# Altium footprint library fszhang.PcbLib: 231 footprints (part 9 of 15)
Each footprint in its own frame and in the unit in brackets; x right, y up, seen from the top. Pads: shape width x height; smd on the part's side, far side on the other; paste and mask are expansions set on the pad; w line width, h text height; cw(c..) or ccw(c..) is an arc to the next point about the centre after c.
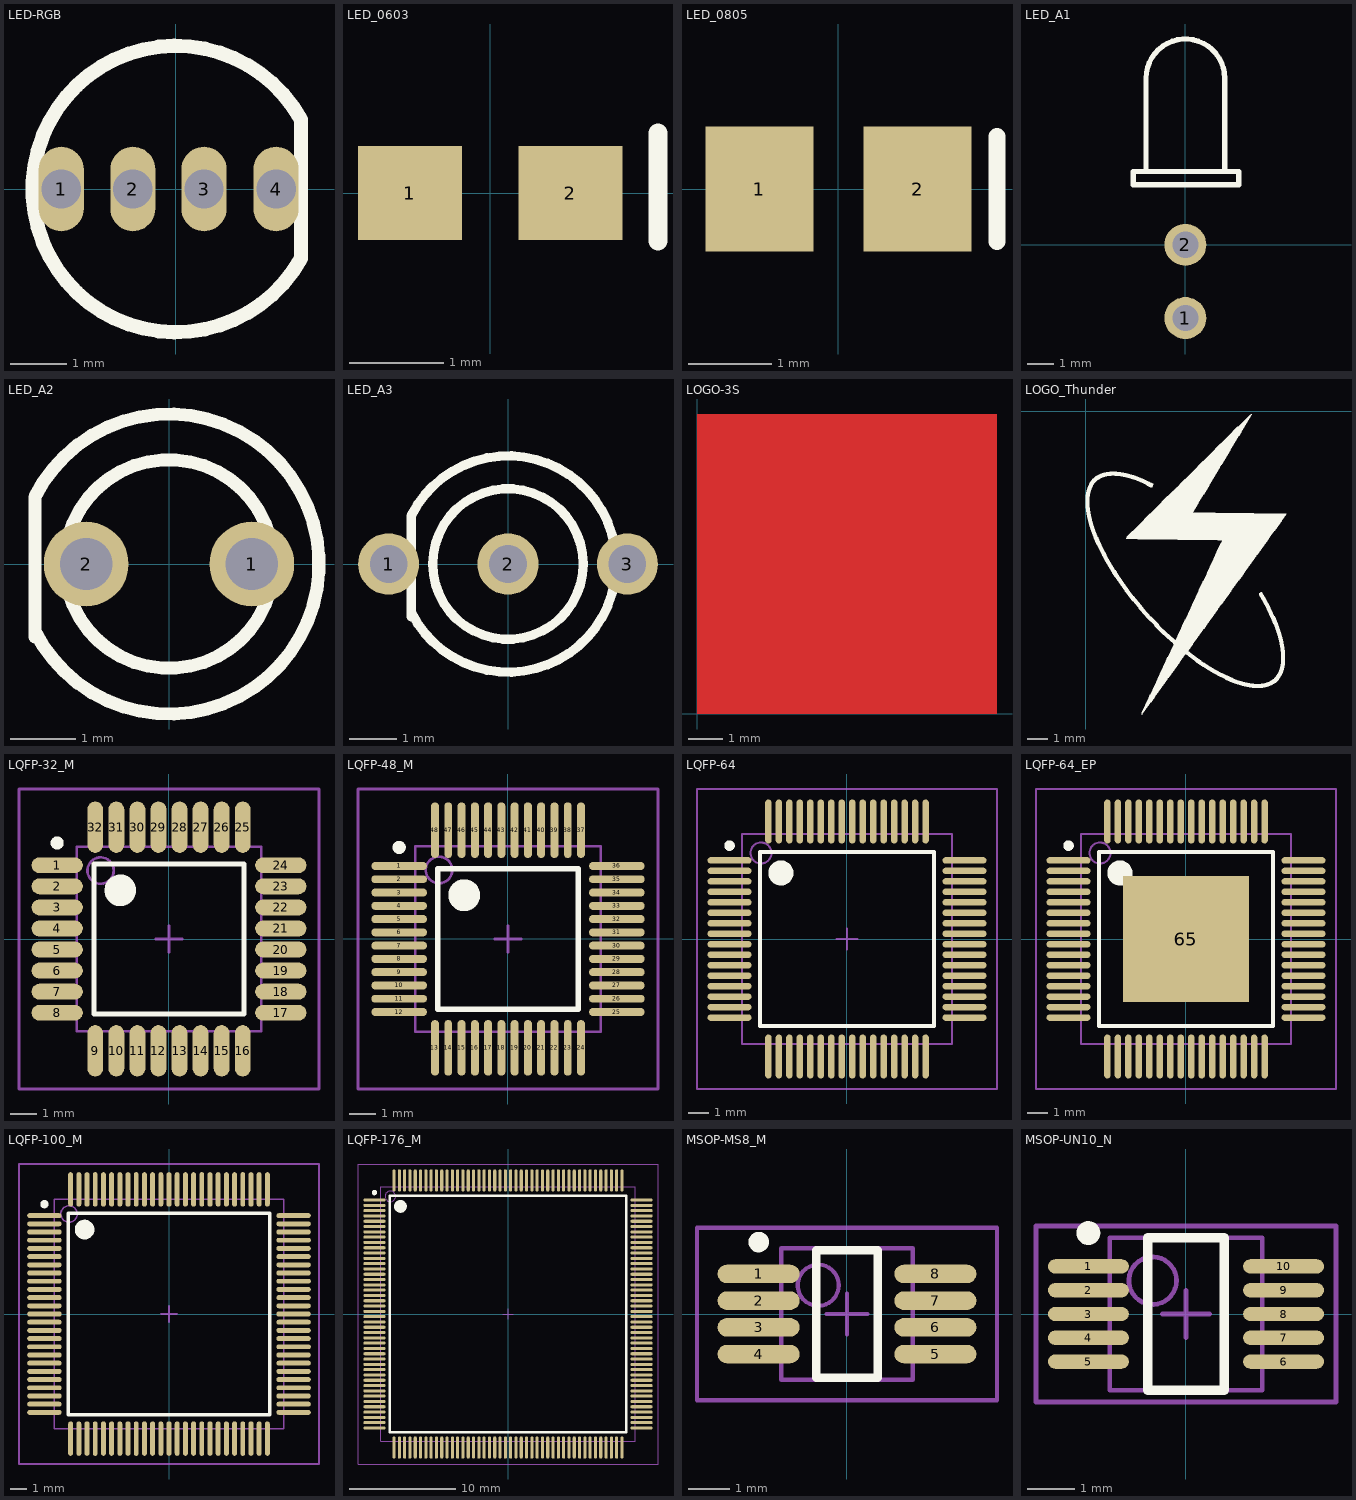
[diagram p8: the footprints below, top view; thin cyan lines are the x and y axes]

## LED-RGB [mm] "三基色二极管"
height 6
pads (4):
  oval 0.8x1.5 hole 0.7: 1(-2.032,0) 2(-0.762,0) 3(0.5,0) 4(1.778,0)
Top Overlay:
  lines w0.254: 2.22,-1.234 cw(c0,0) 2.22,1.234 2.22,-1.234

## LED_0603 [mm] "贴片无丝印"
height 0.6
pads (2):
  rect 1.1x1 smd: 1(-0.85,0) 2(0.85,0)
Top Overlay:
  lines w0.2: 1.778,-0.508 1.778,0.635

## LED_0805 [mm] "贴片二极管"
height 1.1
pads (2):
  rect 1.3x1.5 smd: 1(-0.95,0) 2(0.95,0)
Top Overlay:
  lines w0.2: 1.905,-0.635 1.905,0.635

## LED_A1 [mm] "直径3MM二极管"
height 3.5
pads (2):
  round 1.6 hole 1: 1(0,-2.794) 2(0,0)
Top Overlay:
  lines w0.2: -1.5,2.852 -1.5,6.35 cw(c0,6.35) 1.5,6.35 1.5,2.852 ; -1.984,2.286 2.032,2.286 2.032,2.794 -1.984,2.794 -1.984,2.286

## LED_A2 [mm] "直径3MM二极管"
height 5.5
pads (2):
  round 1.3 hole 0.8: 1(1.27,0) 2(-1.27,0)
Top Overlay:
  circle w0.2: c0,0 r1.6
  lines w0.2: -2.057,-1.118 -2.057,1.029 cw(c0,0) -2.057,-1.029

## LED_A3 [mm] "直径3MM二极管"
height 5.5
pads (3):
  round 1.3 hole 0.8: 1(-2.54,0) 2(0,0) 3(2.54,0)
Top Overlay:
  circle w0.2: c0,0 r1.6
  lines w0.2: -2.057,-1.118 -2.057,1.029 cw(c0,0) -2.057,-1.029

## LOGO-3S [mm]
Top Layer:
  rectangle: 0,0 8.8,8.8
Top Paste:
  circle w1.8: c4.399,4.401 r1.206
  region: 0.203,2.813 2.515,2.813 2.62,2.707 2.709,2.618 2.856,2.491 3.065,2.336 3.371,2.172 3.614,2.078 3.851,2.015 4.117,1.966 4.359,1.95 4.607,1.954 4.874,1.996 5.092,2.052 5.389,2.162 5.606,2.287 5.846,2.43 6.228,2.786 8.473,2.786 8.473,2.787 8.397,2.529 8.283,2.239 8.089,1.886 7.898,1.591 7.641,1.298 7.313,0.995 6.914,0.706 6.524,0.507 6.101,0.348 5.721,0.252 5.216,0.196 0.203,0.196
  region: 0.257,5.8 2.394,5.8 2.304,5.672 2.215,5.504 2.154,5.378 2.095,5.22 2.078,5.162 0.202,4.84 0.202,5.101 0.216,5.429 0.239,5.703
  region: 8.596,5.988 6.284,5.988 6.178,6.094 6.09,6.183 5.942,6.31 5.733,6.465 5.428,6.629 5.185,6.723 4.948,6.786 4.682,6.835 4.44,6.851 4.192,6.847 3.924,6.805 3.706,6.749 3.41,6.639 3.193,6.514 2.953,6.371 2.571,6.015 0.326,6.015 0.326,6.014 0.402,6.272 0.516,6.562 0.71,6.915 0.901,7.21 1.158,7.503 1.485,7.806 1.885,8.095 2.274,8.294 2.698,8.453 3.078,8.549 3.583,8.605 8.596,8.605
  region: 8.525,2.993 6.389,2.993 6.478,3.12 6.568,3.288 6.629,3.414 6.687,3.573 6.705,3.63 8.581,3.953 8.581,3.692 8.566,3.364 8.543,3.09
  region: 8.587,4.147 6.823,4.147 6.831,4.195 6.838,4.282 6.842,4.385 6.84,4.497 6.831,4.6 6.815,4.654 8.587,4.654
  region: 0.203,4.654 1.967,4.654 1.96,4.606 1.952,4.519 1.948,4.416 1.95,4.304 1.96,4.201 1.976,4.147 0.203,4.147
  region: 6.398,5.8 8.576,5.8 8.576,5.137 6.795,4.828 6.77,4.979 6.734,5.098 6.697,5.204 6.619,5.406 6.534,5.58
  region: 2.383,2.992 0.205,2.992 0.205,3.655 1.987,3.964 2.012,3.813 2.047,3.694 2.084,3.589 2.162,3.386 2.247,3.212
Top Solder:
  circle w1.8: c4.398,4.403 r1.206
  region: 0.202,2.815 2.514,2.815 2.62,2.709 2.709,2.62 2.856,2.493 3.065,2.338 3.37,2.174 3.613,2.08 3.85,2.017 4.116,1.968 4.358,1.952 4.606,1.956 4.874,1.998 5.092,2.054 5.388,2.164 5.605,2.289 5.845,2.432 6.228,2.788 8.472,2.788 8.472,2.789 8.396,2.531 8.282,2.241 8.088,1.888 7.897,1.593 7.64,1.3 7.313,0.997 6.913,0.708 6.524,0.509 6.1,0.35 5.72,0.254 5.215,0.198 0.202,0.198
  region: 0.257,5.802 2.393,5.802 2.304,5.674 2.214,5.506 2.153,5.38 2.095,5.222 2.077,5.164 0.201,4.842 0.201,5.103 0.216,5.431 0.239,5.705
  region: 8.595,5.99 6.283,5.99 6.178,6.096 6.089,6.185 5.942,6.312 5.733,6.467 5.427,6.631 5.184,6.725 4.947,6.788 4.681,6.837 4.439,6.853 4.191,6.849 3.924,6.807 3.706,6.751 3.409,6.641 3.192,6.516 2.952,6.373 2.57,6.017 0.325,6.017 0.325,6.016 0.401,6.274 0.515,6.564 0.709,6.917 0.9,7.212 1.157,7.505 1.485,7.808 1.884,8.097 2.274,8.296 2.697,8.455 3.077,8.551 3.582,8.607 8.595,8.607
  region: 8.524,2.995 6.388,2.995 6.477,3.122 6.567,3.29 6.628,3.416 6.687,3.575 6.704,3.632 8.58,3.955 8.58,3.694 8.565,3.366 8.542,3.092
  region: 8.587,4.149 6.823,4.149 6.83,4.197 6.838,4.284 6.841,4.387 6.839,4.499 6.83,4.602 6.814,4.656 8.587,4.656
  region: 0.203,4.656 1.967,4.656 1.959,4.608 1.952,4.521 1.948,4.418 1.95,4.306 1.959,4.203 1.975,4.149 0.203,4.149
  region: 6.397,5.802 8.575,5.802 8.575,5.139 6.794,4.83 6.769,4.981 6.734,5.1 6.697,5.206 6.619,5.408 6.533,5.582
  region: 2.383,2.994 0.205,2.994 0.205,3.657 1.986,3.966 2.011,3.815 2.046,3.696 2.083,3.591 2.161,3.388 2.247,3.214

## LOGO_Thunder [mm]
Top Overlay:
  drawing of 2284 lines, arcs and shapes, not listed

## LQFP-32_M [mm] "Thin QFP, 32-Leads, Body 7x7mm, Pitch 0.8mm, IPC Low Density"
height 1.6
pads (32):
  oval 1.95x0.6 smd: 1(-4.25,2.8) 2(-4.25,2) 3(-4.25,1.2) 4(-4.25,0.4) 5(-4.25,-0.4) 6(-4.25,-1.2) 7(-4.25,-2) 8(-4.25,-2.8) 17(4.25,-2.8) 18(4.25,-2) 19(4.25,-1.2) 20(4.25,-0.4) 21(4.25,0.4) 22(4.25,1.2) 23(4.25,2) 24(4.25,2.8)
  oval 0.6x1.95 smd: 9(-2.8,-4.25) 10(-2,-4.25) 11(-1.2,-4.25) 12(-0.4,-4.25) 13(0.4,-4.25) 14(1.2,-4.25) 15(2,-4.25) 16(2.8,-4.25) 25(2.8,4.25) 26(2,4.25) 27(1.2,4.25) 28(0.4,4.25) 29(-0.4,4.25) 30(-1.2,4.25) 31(-2,4.25) 32(-2.8,4.25)
Top Overlay:
  circle w0.25: c-4.25,3.65 r0.125
  circle w0.6: c-1.85,1.85 r0.3
  lines w0.2: -2.85,-2.85 -2.85,2.85 2.85,2.85 2.85,-2.85 -2.85,-2.85
Mechanical 13:
  circle w0.1: c-2.6,2.6 r0.5
  lines w0.1: -3.5,-3.5 -3.5,3.5 3.5,3.5 3.5,-3.5 -3.5,-3.5
Mechanical 15:
  lines w0.1: -0.5,0 0.5,0 ; 0,-0.5 0,0.5 ; -5.7,-5.7 -5.7,5.7 5.7,5.7 5.7,-5.7 -5.7,-5.7
3D body: height 1.6, standoff 0, extent -3.5,-3.5 3.5,3.5

## LQFP-48_M [mm] "Thin QFP, 48-Leads, Body 7x7mm, Pitch 0.5mm, IPC Low Density"
height 1.6
pads (48):
  oval 2.1x0.3 smd: 1(-4.1,2.75) 2(-4.1,2.25) 3(-4.1,1.75) 4(-4.1,1.25) 5(-4.1,0.75) 6(-4.1,0.25) 7(-4.1,-0.25) 8(-4.1,-0.75) 9(-4.1,-1.25) 10(-4.1,-1.75) 11(-4.1,-2.25) 12(-4.1,-2.75) 25(4.1,-2.75) 26(4.1,-2.25) 27(4.1,-1.75) 28(4.1,-1.25) 29(4.1,-0.75) 30(4.1,-0.25) 31(4.1,0.25) 32(4.1,0.75) 33(4.1,1.25) 34(4.1,1.75) 35(4.1,2.25) 36(4.1,2.75)
  oval 0.3x2.1 smd: 13(-2.75,-4.1) 14(-2.25,-4.1) 15(-1.75,-4.1) 16(-1.25,-4.1) 17(-0.75,-4.1) 18(-0.25,-4.1) 19(0.25,-4.1) 20(0.75,-4.1) 21(1.25,-4.1) 22(1.75,-4.1) 23(2.25,-4.1) 24(2.75,-4.1) 37(2.75,4.1) 38(2.25,4.1) 39(1.75,4.1) 40(1.25,4.1) 41(0.75,4.1) 42(0.25,4.1) 43(-0.25,4.1) 44(-0.75,4.1) 45(-1.25,4.1) 46(-1.75,4.1) 47(-2.25,4.1) 48(-2.75,4.1)
Top Overlay:
  circle w0.6: c-1.65,1.65 r0.3
  circle w0.25: c-4.1,3.45 r0.125
  lines w0.2: -2.65,-2.65 2.65,-2.65 2.65,2.65 -2.65,2.65 -2.65,-2.65
Mechanical 13:
  circle w0.1: c-2.6,2.6 r0.5
  lines w0.1: -3.5,-3.5 3.5,-3.5 3.5,3.5 -3.5,3.5 -3.5,-3.5
Mechanical 15:
  lines w0.1: -0.5,0 0.5,0 ; 0,-0.5 0,0.5 ; -5.65,-5.65 5.65,-5.65 5.65,5.65 -5.65,5.65 -5.65,-5.65
3D body: height 1.6, standoff 0, extent -3.5,-3.5 3.5,3.5

## LQFP-64 [mm] "LQFP64"
height 1.5
pads (64):
  oval 2.1x0.3 smd: 1(-5.6,3.75) 2(-5.6,3.25) 3(-5.6,2.75) 4(-5.6,2.25) 5(-5.6,1.75) 6(-5.6,1.25) 7(-5.6,0.75) 8(-5.6,0.25) 9(-5.6,-0.25) 10(-5.6,-0.75) 11(-5.6,-1.25) 12(-5.6,-1.75) 13(-5.6,-2.25) 14(-5.6,-2.75) 15(-5.6,-3.25) 16(-5.6,-3.75) 33(5.6,-3.75) 34(5.6,-3.25) 35(5.6,-2.75) 36(5.6,-2.25) 37(5.6,-1.75) 38(5.6,-1.25) 39(5.6,-0.75) 40(5.6,-0.25) 41(5.6,0.25) 42(5.6,0.75) 43(5.6,1.25) 44(5.6,1.75) 45(5.6,2.25) 46(5.6,2.75) 47(5.6,3.25) 48(5.6,3.75)
  oval 0.3x2.1 smd: 17(-3.75,-5.6) 18(-3.25,-5.6) 19(-2.75,-5.6) 20(-2.25,-5.6) 21(-1.75,-5.6) 22(-1.25,-5.6) 23(-0.75,-5.6) 24(-0.25,-5.6) 25(0.25,-5.6) 26(0.75,-5.6) 27(1.25,-5.6) 28(1.75,-5.6) 29(2.25,-5.6) 30(2.75,-5.6) 31(3.25,-5.6) 32(3.75,-5.6) 49(3.75,5.6) 50(3.25,5.6) 51(2.75,5.6) 52(2.25,5.6) 53(1.75,5.6) 54(1.25,5.6) 55(0.75,5.6) 56(0.25,5.6) 57(-0.25,5.6) 58(-0.75,5.6) 59(-1.25,5.6) 60(-1.75,5.6) 61(-2.25,5.6) 62(-2.75,5.6) 63(-3.25,5.6) 64(-3.75,5.6)
Top Overlay:
  circle w0.6: c-3.15,3.15 r0.3
  circle w0.25: c-5.6,4.45 r0.125
  lines w0.2: -4.15,-4.15 4.15,-4.15 4.15,4.15 -4.15,4.15 -4.15,-4.15
Mechanical 13:
  circle w0.1: c-4.1,4.1 r0.5
  lines w0.1: -5,-5 5,-5 5,5 -5,5 -5,-5
Mechanical 15:
  lines w0.1: -0.5,0 0.5,0 ; 0,-0.5 0,0.5 ; -7.15,-7.15 7.15,-7.15 7.15,7.15 -7.15,7.15 -7.15,-7.15
3D body: height 1.6, standoff 0, extent -5,-5 5,5

## LQFP-64_EP [mm] "LQFP64"
height 1.5
pads (65):
  oval 2.1x0.3 smd: 1(-5.6,3.75) 2(-5.6,3.25) 3(-5.6,2.75) 4(-5.6,2.25) 5(-5.6,1.75) 6(-5.6,1.25) 7(-5.6,0.75) 8(-5.6,0.25) 9(-5.6,-0.25) 10(-5.6,-0.75) 11(-5.6,-1.25) 12(-5.6,-1.75) 13(-5.6,-2.25) 14(-5.6,-2.75) 15(-5.6,-3.25) 16(-5.6,-3.75) 33(5.6,-3.75) 34(5.6,-3.25) 35(5.6,-2.75) 36(5.6,-2.25) 37(5.6,-1.75) 38(5.6,-1.25) 39(5.6,-0.75) 40(5.6,-0.25) 41(5.6,0.25) 42(5.6,0.75) 43(5.6,1.25) 44(5.6,1.75) 45(5.6,2.25) 46(5.6,2.75) 47(5.6,3.25) 48(5.6,3.75)
  oval 0.3x2.1 smd: 17(-3.75,-5.6) 18(-3.25,-5.6) 19(-2.75,-5.6) 20(-2.25,-5.6) 21(-1.75,-5.6) 22(-1.25,-5.6) 23(-0.75,-5.6) 24(-0.25,-5.6) 25(0.25,-5.6) 26(0.75,-5.6) 27(1.25,-5.6) 28(1.75,-5.6) 29(2.25,-5.6) 30(2.75,-5.6) 31(3.25,-5.6) 32(3.75,-5.6) 49(3.75,5.6) 50(3.25,5.6) 51(2.75,5.6) 52(2.25,5.6) 53(1.75,5.6) 54(1.25,5.6) 55(0.75,5.6) 56(0.25,5.6) 57(-0.25,5.6) 58(-0.75,5.6) 59(-1.25,5.6) 60(-1.75,5.6) 61(-2.25,5.6) 62(-2.75,5.6) 63(-3.25,5.6) 64(-3.75,5.6)
  rect 6x6 smd: 65(0,0)
Top Overlay:
  circle w0.25: c-5.6,4.45 r0.125
  circle w0.6: c-3.15,3.15 r0.3
  lines w0.2: -4.15,-4.15 -4.15,4.15 4.15,4.15 4.15,-4.15 -4.15,-4.15
Mechanical 13:
  circle w0.1: c-4.1,4.1 r0.5
  lines w0.1: -5,-5 -5,5 5,5 5,-5 -5,-5
Mechanical 15:
  lines w0.1: -0.5,0 0.5,0 ; 0,-0.5 0,0.5 ; -7.15,-7.15 -7.15,7.15 7.15,7.15 7.15,-7.15 -7.15,-7.15
3D body: height 1.6, standoff 0, extent -5,-5 5,5

## LQFP-100_M [mm] "Thin QFP, 100"
height 1.6
pads (100):
  oval 2.1x0.3 smd: 1(-7.6,6) 2(-7.6,5.5) 3(-7.6,5) 4(-7.6,4.5) 5(-7.6,4) 6(-7.6,3.5) 7(-7.6,3) 8(-7.6,2.5) 9(-7.6,2) 10(-7.6,1.5) 11(-7.6,1) 12(-7.6,0.5) 13(-7.6,0) 14(-7.6,-0.5) 15(-7.6,-1) 16(-7.6,-1.5) 17(-7.6,-2) 18(-7.6,-2.5) 19(-7.6,-3) 20(-7.6,-3.5) 21(-7.6,-4) 22(-7.6,-4.5) 23(-7.6,-5) 24(-7.6,-5.5) 25(-7.6,-6) 51(7.6,-6) 52(7.6,-5.5) 53(7.6,-5) 54(7.6,-4.5) 55(7.6,-4) 56(7.6,-3.5) 57(7.6,-3) 58(7.6,-2.5) 59(7.6,-2) 60(7.6,-1.5) 61(7.6,-1) 62(7.6,-0.5) 63(7.6,0) 64(7.6,0.5) 65(7.6,1) 66(7.6,1.5) 67(7.6,2) 68(7.6,2.5) 69(7.6,3) 70(7.6,3.5) 71(7.6,4) 72(7.6,4.5) 73(7.6,5) 74(7.6,5.5) 75(7.6,6)
  oval 0.3x2.1 smd: 26(-6,-7.6) 27(-5.5,-7.6) 28(-5,-7.6) 29(-4.5,-7.6) 30(-4,-7.6) 31(-3.5,-7.6) 32(-3,-7.6) 33(-2.5,-7.6) 34(-2,-7.6) 35(-1.5,-7.6) 36(-1,-7.6) 37(-0.5,-7.6) 38(0,-7.6) 39(0.5,-7.6) 40(1,-7.6) 41(1.5,-7.6) 42(2,-7.6) 43(2.5,-7.6) 44(3,-7.6) 45(3.5,-7.6) 46(4,-7.6) 47(4.5,-7.6) 48(5,-7.6) 49(5.5,-7.6) 50(6,-7.6) 76(6,7.6) 77(5.5,7.6) 78(5,7.6) 79(4.5,7.6) 80(4,7.6) 81(3.5,7.6) 82(3,7.6) 83(2.5,7.6) 84(2,7.6) 85(1.5,7.6) 86(1,7.6) 87(0.5,7.6) 88(0,7.6) 89(-0.5,7.6) 90(-1,7.6) 91(-1.5,7.6) 92(-2,7.6) 93(-2.5,7.6) 94(-3,7.6) 95(-3.5,7.6) 96(-4,7.6) 97(-4.5,7.6) 98(-5,7.6) 99(-5.5,7.6) 100(-6,7.6)
Top Overlay:
  circle w0.6: c-5.15,5.15 r0.3
  circle w0.25: c-7.6,6.7 r0.125
  lines w0.2: -6.15,-6.15 6.15,-6.15 6.15,6.15 -6.15,6.15 -6.15,-6.15
Mechanical 13:
  circle w0.1: c-6.1,6.1 r0.5
  lines w0.1: -7,-7 7,-7 7,7 -7,7 -7,-7
Mechanical 15:
  lines w0.1: -0.5,0 0.5,0 ; 0,-0.5 0,0.5 ; -9.15,-9.15 9.15,-9.15 9.15,9.15 -9.15,9.15 -9.15,-9.15
3D body: height 0.8, standoff 0, extent -7,-7 7,7

## LQFP-176_M [mm] "Thin QFP, 176-Leads, Body 24x24mm, Pitch 0.5mm, IPC Low Density"
height 1.6
pads (176):
  oval 2.1x0.3 smd: 1(-12.6,10.75) 2(-12.6,10.25) 3(-12.6,9.75) 4(-12.6,9.25) 5(-12.6,8.75) 6(-12.6,8.25) 7(-12.6,7.75) 8(-12.6,7.25) 9(-12.6,6.75) 10(-12.6,6.25) 11(-12.6,5.75) 12(-12.6,5.25) 13(-12.6,4.75) 14(-12.6,4.25) 15(-12.6,3.75) 16(-12.6,3.25) 17(-12.6,2.75) 18(-12.6,2.25) 19(-12.6,1.75) 20(-12.6,1.25) 21(-12.6,0.75) 22(-12.6,0.25) 23(-12.6,-0.25) 24(-12.6,-0.75) 25(-12.6,-1.25) 26(-12.6,-1.75) 27(-12.6,-2.25) 28(-12.6,-2.75) 29(-12.6,-3.25) 30(-12.6,-3.75) 31(-12.6,-4.25) 32(-12.6,-4.75) 33(-12.6,-5.25) 34(-12.6,-5.75) 35(-12.6,-6.25) 36(-12.6,-6.75) 37(-12.6,-7.25) 38(-12.6,-7.75) 39(-12.6,-8.25) 40(-12.6,-8.75) 41(-12.6,-9.25) 42(-12.6,-9.75) 43(-12.6,-10.25) 44(-12.6,-10.75) 89(12.6,-10.75) 90(12.6,-10.25) 91(12.6,-9.75) 92(12.6,-9.25) 93(12.6,-8.75) 94(12.6,-8.25) 95(12.6,-7.75) 96(12.6,-7.25) 97(12.6,-6.75) 98(12.6,-6.25) 99(12.6,-5.75) 100(12.6,-5.25) 101(12.6,-4.75) 102(12.6,-4.25) 103(12.6,-3.75) 104(12.6,-3.25) 105(12.6,-2.75) 106(12.6,-2.25) 107(12.6,-1.75) 108(12.6,-1.25) 109(12.6,-0.75) 110(12.6,-0.25) 111(12.6,0.25) 112(12.6,0.75) 113(12.6,1.25) 114(12.6,1.75) 115(12.6,2.25) 116(12.6,2.75) 117(12.6,3.25) 118(12.6,3.75) 119(12.6,4.25) 120(12.6,4.75) 121(12.6,5.25) 122(12.6,5.75) 123(12.6,6.25) 124(12.6,6.75) 125(12.6,7.25) 126(12.6,7.75) 127(12.6,8.25) 128(12.6,8.75) 129(12.6,9.25) 130(12.6,9.75) 131(12.6,10.25) 132(12.6,10.75)
  oval 0.3x2.1 smd: 45(-10.75,-12.6) 46(-10.25,-12.6) 47(-9.75,-12.6) 48(-9.25,-12.6) 49(-8.75,-12.6) 50(-8.25,-12.6) 51(-7.75,-12.6) 52(-7.25,-12.6) 53(-6.75,-12.6) 54(-6.25,-12.6) 55(-5.75,-12.6) 56(-5.25,-12.6) 57(-4.75,-12.6) 58(-4.25,-12.6) 59(-3.75,-12.6) 60(-3.25,-12.6) 61(-2.75,-12.6) 62(-2.25,-12.6) 63(-1.75,-12.6) 64(-1.25,-12.6) 65(-0.75,-12.6) 66(-0.25,-12.6) 67(0.25,-12.6) 68(0.75,-12.6) 69(1.25,-12.6) 70(1.75,-12.6) 71(2.25,-12.6) 72(2.75,-12.6) 73(3.25,-12.6) 74(3.75,-12.6) 75(4.25,-12.6) 76(4.75,-12.6) 77(5.25,-12.6) 78(5.75,-12.6) 79(6.25,-12.6) 80(6.75,-12.6) 81(7.25,-12.6) 82(7.75,-12.6) 83(8.25,-12.6) 84(8.75,-12.6) 85(9.25,-12.6) 86(9.75,-12.6) 87(10.25,-12.6) 88(10.75,-12.6) 133(10.75,12.6) 134(10.25,12.6) 135(9.75,12.6) 136(9.25,12.6) 137(8.75,12.6) 138(8.25,12.6) 139(7.75,12.6) 140(7.25,12.6) 141(6.75,12.6) 142(6.25,12.6) 143(5.75,12.6) 144(5.25,12.6) 145(4.75,12.6) 146(4.25,12.6) 147(3.75,12.6) 148(3.25,12.6) 149(2.75,12.6) 150(2.25,12.6) 151(1.75,12.6) 152(1.25,12.6) 153(0.75,12.6) 154(0.25,12.6) 155(-0.25,12.6) 156(-0.75,12.6) 157(-1.25,12.6) 158(-1.75,12.6) 159(-2.25,12.6) 160(-2.75,12.6) 161(-3.25,12.6) 162(-3.75,12.6) 163(-4.25,12.6) 164(-4.75,12.6) 165(-5.25,12.6) 166(-5.75,12.6) 167(-6.25,12.6) 168(-6.75,12.6) 169(-7.25,12.6) 170(-7.75,12.6) 171(-8.25,12.6) 172(-8.75,12.6) 173(-9.25,12.6) 174(-9.75,12.6) 175(-10.25,12.6) 176(-10.75,12.6)
Top Overlay:
  circle w0.6: c-10.15,10.15 r0.3
  circle w0.25: c-12.6,11.45 r0.125
  lines w0.2: -11.15,-11.15 11.15,-11.15 11.15,11.15 -11.15,11.15 -11.15,-11.15
Mechanical 13:
  circle w0.1: c-11.1,11.1 r0.5
  lines w0.1: -12,-12 12,-12 12,12 -12,12 -12,-12
Mechanical 15:
  lines w0.1: -0.5,0 0.5,0 ; 0,-0.5 0,0.5 ; -14.15,-14.15 14.15,-14.15 14.15,14.15 -14.15,14.15 -14.15,-14.15
3D body: height 1.6, standoff 0, extent -12,-12 12,12

## MSOP-MS8_M [mm] "TSOP, 8-Leads, Body 3x3mm, Pitch 0.65mm, IPC Low Density"
height 1.1
pads (8):
  oval 2x0.45 smd: 1(-2.15,0.975) 2(-2.15,0.325) 3(-2.15,-0.325) 4(-2.15,-0.975) 5(2.15,-0.975) 6(2.15,-0.325) 7(2.15,0.325) 8(2.15,0.975)
Top Overlay:
  circle w0.25: c-2.15,1.75 r0.125
  lines w0.2: -0.75,-1.55 0.75,-1.55 0.75,1.55 -0.75,1.55 -0.75,-1.55
Mechanical 13:
  circle w0.1: c-0.7,0.7 r0.5
  lines w0.1: -1.6,-1.6 1.6,-1.6 1.6,1.6 -1.6,1.6 -1.6,-1.6
Mechanical 15:
  lines w0.1: -0.5,0 0.5,0 ; 0,-0.5 0,0.5 ; -3.65,-2.1 3.65,-2.1 3.65,2.1 -3.65,2.1 -3.65,-2.1
3D body: height 1.1, standoff 0, extent -1.6,-1.6 1.6,1.6

## MSOP-UN10_N [mm] "TSSOP"
height 1.1
pads (10):
  oval 1.7x0.3 smd: 1(-2.05,1) 2(-2.05,0.5) 3(-2.05,0) 4(-2.05,-0.5) 5(-2.05,-1) 6(2.05,-1) 7(2.05,-0.5) 8(2.05,0) 9(2.05,0.5) 10(2.05,1)
Top Overlay:
  circle w0.25: c-2.05,1.7 r0.125
  lines w0.2: -0.8,-1.6 0.8,-1.6 0.8,1.6 -0.8,1.6 -0.8,-1.6
Mechanical 13:
  circle w0.1: c-0.7,0.7 r0.5
  lines w0.1: -1.6,-1.6 1.6,-1.6 1.6,1.6 -1.6,1.6 -1.6,-1.6
Mechanical 15:
  lines w0.1: -0.5,0 0.5,0 ; 0,-0.5 0,0.5 ; -3.15,-1.85 3.15,-1.85 3.15,1.85 -3.15,1.85 -3.15,-1.85
3D body: height 1.1, standoff 0, extent -1.6,-1.6 1.6,1.6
